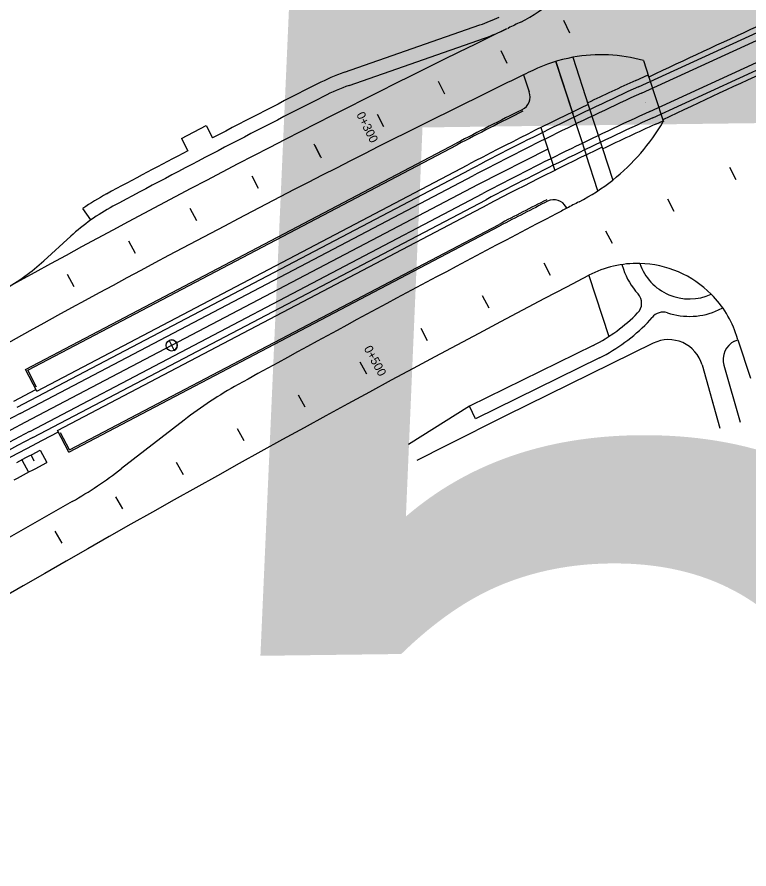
# Model space of a CAD drawing. Extents: x 6503541 to 6503743, y 5888004 to 5888145.
# Drawn here: x 6503602.995 to 6503605.517, y 5888053.223 to 5888056.159 of the extents above; entities that cross this region are included whole.
import ezdxf

# ---------------------------------------------------------------- set-up
doc = ezdxf.new("R2010")
doc.units = 0
doc.layers.add('12', color=7, linetype='Continuous')

msp = doc.modelspace()

# ---------------------------------------------------------------- linework, layer by layer
at = {"layer": '12'}
for p, q in [((6503605.1366, 5888055.919), (6503621.1114, 5888063.2433)), ((6503605.1466, 5888055.8972), (6503621.1214, 5888063.2215)), ((6503605.1756, 5888055.8339), (6503621.1505, 5888063.1582)), ((6503605.1856, 5888055.8121), (6503621.1605, 5888063.1364)), ((6503604.1237, 5888055.9686), (6503604.5898, 5888056.1319)), ((6503604.1396, 5888055.9233), (6503604.6057, 5888056.0866)), ((6503604.8516, 5888056.0062), (6503604.9097, 5888055.8272)), ((6503604.9083, 5888055.8314), (6503604.8516, 5888056.0062)), ((6503604.9101, 5888056.0203), (6503604.9643, 5888055.8535)), ((6503605.1535, 5888056.0088), (6503605.1719, 5888055.9523)), ((6503604.7404, 5888055.9599), (6503604.7596, 5888055.9009)), ((6503605.1266, 5888055.9408), (6503605.1693, 5888055.9604)), ((6503605.1719, 5888055.9523), (6503605.1693, 5888055.9604)), ((6503605.1719, 5888055.9523), (6503605.2197, 5888055.8051)), ((6503605.1719, 5888055.9523), (6503605.2197, 5888055.8051)), ((6503604.9643, 5888055.8535), (6503605.0122, 5888055.7061)), ((6503604.9576, 5888055.6798), (6503604.9097, 5888055.8272)), ((6503605.1956, 5888055.7903), (6503605.2208, 5888055.8018)), ((6503605.2197, 5888055.8051), (6503605.2217, 5888055.799)), ((6503605.2197, 5888055.8051), (6503605.2208, 5888055.8018)), ((6503603.5618, 5888055.7409), (6503603.6468, 5888055.7855)), ((6503603.6468, 5888055.7855), (6503603.6691, 5888055.743)), ((6503604.7995, 5888055.7781), (6503604.8475, 5888055.6305)), ((6503603.5618, 5888055.7409), (6503603.5841, 5888055.6984)), ((6503603.0239, 5888054.9444), (6503604.5089, 5888055.7242)), ((6503603.032, 5888054.9419), (6503604.5117, 5888055.7188)), ((6503604.8235, 5888055.7043), (6503604.5837, 5888055.5818)), ((6503605.0122, 5888055.7061), (6503605.0474, 5888055.5975)), ((6503604.9964, 5888055.5605), (6503604.9563, 5888055.6839)), ((6503604.9964, 5888055.5605), (6503604.9563, 5888055.6839)), ((6503603.0629, 5888054.87), (6503604.548, 5888055.6498)), ((6503602.9952, 5888054.8142), (6503604.5563, 5888055.6339)), ((6503603.0064, 5888054.7929), (6503604.5675, 5888055.6126)), ((6503604.5837, 5888055.5818), (6503603.0226, 5888054.7621)), ((6503603.0388, 5888054.7313), (6503604.5998, 5888055.551)), ((6503603.0499, 5888054.71), (6503604.611, 5888055.5297)), ((6503603.1343, 5888054.734), (6503604.6194, 5888055.5138)), ((6503603.2498, 5888055.4599), (6503603.222, 5888055.4991)), ((6503604.8886, 5888055.5013), (6503604.887, 5888055.5044)), ((6503604.887, 5888055.5044), (6503604.8892, 5888055.5003)), ((6503603.1734, 5888054.6597), (6503604.6584, 5888055.4394)), ((6503603.1759, 5888054.6678), (6503604.6556, 5888055.4447)), ((6503603.0877, 5888055.3192), (6503603.1802, 5888055.4038)), ((6503605.079, 5888055.3061), (6503605.084, 5888055.2907)), ((6503604.9634, 5888055.2683), (6503604.9649, 5888055.2691)), ((6503604.9648, 5888055.269), (6503605.0334, 5888055.058)), ((6503605.4118, 5888055.1496), (6503605.4262, 5888055.1569)), ((6503605.1673, 5888055.1056), (6503605.1829, 5888055.124)), ((6503605.4788, 5888055.0465), (6503605.474, 5888055.0612)), ((6503604.9803, 5888055.0273), (6503604.5539, 5888054.818)), ((6503605.1869, 5888055.0351), (6503604.6806, 5888054.7866)), ((6503605.4667, 5888055.0426), (6503605.4788, 5888055.0465)), ((6503605.4788, 5888055.0465), (6503605.5216, 5888054.9146)), ((6503605.0022, 5888054.9846), (6503604.575, 5888054.775)), ((6503603.0629, 5888054.87), (6503603.0239, 5888054.9444)), ((6503603.0627, 5888054.8834), (6503603.032, 5888054.9419)), ((6503605.3552, 5888054.9601), (6503605.4168, 5888054.7426)), ((6503605.4304, 5888054.9589), (6503605.4867, 5888054.7625)), ((6503602.9841, 5888054.8354), (6503603.0601, 5888054.8753)), ((6503605.3866, 5888054.8494), (6503605.4168, 5888054.7426)), ((6503604.5539, 5888054.818), (6503604.3442, 5888054.6861)), ((6503604.575, 5888054.775), (6503604.5539, 5888054.818)), ((6503603.0226, 5888054.7621), (6503602.6797, 5888054.5776)), ((6503603.5709, 5888054.7702), (6503603.3549, 5888054.6029)), ((6503604.6806, 5888054.7866), (6503604.4742, 5888054.6832)), ((6503603.1734, 5888054.6597), (6503603.1343, 5888054.734)), ((6503603.1759, 5888054.6678), (6503603.1452, 5888054.7262)), ((6503604.4742, 5888054.6832), (6503604.372, 5888054.6314)), ((6503603.0548, 5888054.6286), (6503603.0434, 5888054.6502)), ((6503603.0753, 5888054.667), (6503603.098, 5888054.6237)), ((6503603.0116, 5888054.6334), (6503603.0344, 5888054.5904))]:
    msp.add_line(p, q, dxfattribs=at)
for points in [[(6503604.8999, 5888056.1034), (6503604.8792, 5888056.1467)], [(6503604.6839, 5888055.9992), (6503604.6629, 5888056.0423)], [(6503604.4686, 5888055.8935), (6503604.4473, 5888055.9365)], [(6503604.2364, 5888055.8246), (6503604.258, 5888055.7817)], [(6503604.0401, 5888055.6779), (6503604.0183, 5888055.7207)], [(6503604.0441, 5888055.6732), (6503604.0222, 5888055.716)], [(6503605.4729, 5888055.5983), (6503605.4511, 5888055.6411)], [(6503603.8269, 5888055.568), (6503603.8048, 5888055.6106)], [(6503605.2592, 5888055.4892), (6503605.2373, 5888055.5319)], [(6503603.6145, 5888055.4567), (6503603.5921, 5888055.4992)], [(6503605.0461, 5888055.379), (6503605.024, 5888055.4216)], [(6503603.4028, 5888055.344), (6503603.3801, 5888055.3863)], [(6503604.8335, 5888055.268), (6503604.8112, 5888055.3105)], [(6503603.1918, 5888055.2299), (6503603.1689, 5888055.272)], [(6503604.6214, 5888055.156), (6503604.5988, 5888055.1984)], [(6503604.4097, 5888055.043), (6503604.387, 5888055.0853)], [(6503603.5188, 5888055.0444), (6503603.5367, 5888055.0104)], [(6503604.1757, 5888054.9713), (6503604.1986, 5888054.9291)], [(6503603.988, 5888054.8143), (6503603.9649, 5888054.8564)], [(6503603.7779, 5888054.6985), (6503603.7546, 5888054.7405)], [(6503602.9945, 5888054.6243), (6503603.0051, 5888054.6299), (6503603.0156, 5888054.6355), (6503603.0261, 5888054.6411), (6503603.0367, 5888054.6467), (6503603.0473, 5888054.6522), (6503603.0753, 5888054.667)], [(6503602.9859, 5888054.5645), (6503602.9964, 5888054.5701), (6503603.0069, 5888054.5757), (6503603.0174, 5888054.5813), (6503603.0279, 5888054.5869), (6503603.0384, 5888054.5925), (6503603.0489, 5888054.598), (6503603.0595, 5888054.6035), (6503603.07, 5888054.6091), (6503603.098, 5888054.6237)], [(6503603.5683, 5888054.5818), (6503603.5448, 5888054.6237)], [(6503603.3592, 5888054.4642), (6503603.3356, 5888054.5059)], [(6503603.1506, 5888054.3456), (6503603.1268, 5888054.3873)]]:
    msp.add_lwpolyline(points, dxfattribs=at)
msp.add_circle((6503603.5278, 5888055.0274), 0.0192, dxfattribs=at)
for centre, radius, start, end in [((6503604.5424, 5888056.5307), 0.432, 295.7869, 314.4291), ((6503604.3677, 5888056.7661), 0.672, 289.2984, 295.3978), ((6503620.5817, 5888023.3322), 36.438, 115.78687, 115.86075), ((6503620.5817, 5888023.3322), 36.438, 115.87142, 118.93897), ((6503604.3677, 5888056.7661), 0.72, 289.2984, 295.8714), ((6503620.5817, 5888023.3322), 36.438, 115.86075, 115.87142), ((6503620.5817, 5888023.3322), 36.0768, 114.63106, 115.28623), ((6503620.5817, 5888023.3322), 36.0768, 114.63106, 115.28623), ((6503605.007, 5888055.489), 0.54, 74.2494, 100.3361), ((6503605.007, 5888055.489), 0.54, 100.3361, 115.8427), ((6503605.007, 5888055.489), 0.54, 100.3361, 115.8427), ((6503604.3775, 5888055.2438), 0.768, 109.2984, 116.9208), ((6503620.5817, 5888023.3322), 36.27, 115.8427, 115.8974), ((6503620.5817, 5888023.3322), 36.27, 115.8427, 115.8974), ((6503620.5817, 5888023.3322), 35.9232, 114.63106, 115.31741), ((6503620.5817, 5888023.3322), 35.9232, 114.63106, 115.31741), ((6503620.5817, 5888023.3322), 36.27, 115.8974, 116.09163), ((6503610.1624, 5888044.9574), 12.0828, 114.63106, 115.49766), ((6503620.5817, 5888023.3322), 36.27, 116.09163, 121.5843), ((6503620.5817, 5888023.3322), 36.558, 116.92078, 117.5565), ((6503604.3775, 5888055.2438), 0.72, 109.2984, 116.9208), ((6503610.1624, 5888044.9574), 12.0588, 114.63106, 117.70332), ((6503620.5817, 5888023.3322), 36.51, 116.92078, 118.20556), ((6503610.1624, 5888044.9574), 12.0348, 114.63106, 117.70332), ((6503604.7146, 5888055.8836), 0.0482, 294.8724, 21.0628), ((6503610.1624, 5888044.9574), 12.0768, 115.5014, 117.70332), ((6503610.1624, 5888044.9574), 12.1608, 116.50716, 117.70332), ((6503610.1624, 5888044.9574), 12.1548, 116.50716, 117.70332), ((6503610.1624, 5888044.9574), 11.9652, 114.63106, 117.70332), ((6503610.1624, 5888044.9574), 11.9412, 114.63106, 117.70332), ((6503610.1624, 5888044.9574), 11.9172, 114.63106, 115.60248), ((6503604.5993, 5888056.1611), 0.72, 308.4857, 329.8087), ((6503620.5817, 5888023.3322), 35.9232, 115.31741, 115.31756), ((6503610.1624, 5888044.9574), 11.9232, 115.59863, 117.70332), ((6503620.5817, 5888023.3322), 36.558, 117.70696, 118.20556), ((6503604.5993, 5888056.1611), 0.72, 297.4913, 308.4857), ((6503604.5993, 5888056.1611), 0.72, 297.4913, 308.4857), ((6503603.6661, 5888054.8725), 0.768, 118.2056, 125.3226), ((6503610.1624, 5888044.9574), 11.8452, 116.8064, 117.70332), ((6503610.1624, 5888044.9574), 11.8392, 116.8064, 117.70332), ((6503604.8448, 5888055.4815), 0.048, 28.5471, 116.8064), ((6503603.6661, 5888054.8725), 0.72, 118.2056, 132.4397), ((6503629.9308, 5888007.4817), 54.156, 117.54198, 117.58618), ((6503629.9308, 5888007.4817), 54.156, 117.49127, 117.54198), ((6503629.9308, 5888007.4817), 54.156, 117.49127, 117.54198), ((6503629.9308, 5888007.4817), 54.156, 117.58618, 118.90144), ((6503602.6018, 5888055.8505), 0.72, 298.939, 312.4397), ((6503605.1316, 5888054.95), 0.36, 88.5249, 117.5842), ((6503605.3114, 5888055.3676), 0.24, 198.6876, 222.4893), ((6503605.3114, 5888055.3676), 0.18, 198.6876, 294.724), ((6503605.1316, 5888054.95), 0.36, 44.8866, 88.5249), ((6503629.9308, 5888007.4817), 53.916, 117.58603, 123.39571), ((6503629.9308, 5888007.4817), 53.916, 117.58424, 117.58603), ((6503605.099, 5888055.173), 0.048, 315.3788, 42.4893), ((6503605.1316, 5888054.95), 0.36, 17.9994, 44.8582), ((6503605.2206, 5888055.0943), 0.048, 71.618, 141.7344), ((6503605.3114, 5888055.3676), 0.24, 251.618, 294.724), ((6503604.7089, 5888055.558), 0.5961, 297.0831, 315.3788), ((6503604.7089, 5888055.558), 0.6441, 297.0831, 315.3788), ((6503603.5278, 5888055.0274), 0.0192, 353.2561, 117.7033), ((6503603.5278, 5888055.0274), 0.0192, 297.7033, 353.2561), ((6503605.2397, 5888054.9274), 0.12, 15.8262, 116.138), ((6503605.4996, 5888054.9786), 0.072, 117.2201, 195.8262), ((6503604.453, 5888053.632), 1.44, 118.9014, 127.7727), ((6503611.9485, 5888037.7631), 19.2348, 117.70332, 123.39571), ((6503611.9485, 5888037.7631), 19.1652, 117.70332, 123.39571), ((6503611.9485, 5888037.7631), 19.1412, 117.70332, 123.39571), ((6503611.9485, 5888037.7631), 19.1172, 117.44544, 123.39571), ((6503602.4729, 5888055.7411), 1.44, 299.6384, 307.7727), ((6503629.9308, 5888007.4817), 54.084, 119.63838, 123.39571)]:
    msp.add_arc(centre, radius, start, end, dxfattribs=at)

# ---------------------------------------------------------------- texts
for s, height, rotation, p in [('5', 4.223, 0.7393, (6503603.5197, 5888052.0026)), ('C', 0.0024, 24.6311, (6503605.1605, 5888055.8639)), ('0+300', 0.03, 296.7051, (6503604.1633, 5888055.823)), ('C', 0.0024, 27.7033, (6503604.5831, 5888055.5802)), ('0+500', 0.03, 298.4724, (6503604.1891, 5888055.017)), ('C', 0.0024, 27.7033, (6503603.0221, 5888054.7605))]:
    msp.add_text(s, height=height, rotation=rotation, dxfattribs=at).set_placement(p)

doc.saveas('drawing.dxf')
